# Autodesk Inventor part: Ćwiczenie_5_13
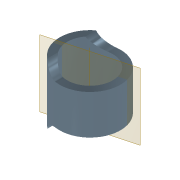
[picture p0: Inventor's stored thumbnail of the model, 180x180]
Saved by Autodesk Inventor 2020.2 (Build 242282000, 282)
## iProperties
Created: 2005-02
Part Number: Ćwiczenie_5_13
Document SubType Name: Modeling
Designer: F.Stasiak
Manufacturer: Standard
Standards Organization: Custom
Density: 1 g/cm^3
Material: Ogólny
Appearance: Nikiel (jasny)
Manager: www.cadconsulting.pl
Company: Fabian Stasiak CAD Consulting
Author: F.Stasiak
Subject: Zbiór ćwiczeń. Autodesk Inventor 2020. Kurs podstawowy
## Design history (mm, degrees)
sketch "Szkic1"
  geometry: C1 r 20 at (0, 0); 1 further point
  constraints: 1 centre point, 1 coincident
  dimensions: "d0" = 40 diameter of C1
extrude "Wyciągnięcie proste1" new body sketch "Szkic1" stored distance "d1" = 40; taper "d2" = 0 deg
sketch "Szkic2"
  geometry: L1 (20, -20)-(-20, -20) reference; L2 (-20, -20)-(-20, 20) reference; L3 (-20, 20)-(20, 20) reference; L4 (20, 20)-(20, -20) reference; L5 (20, 13)-(-2.461, 13); A1 r 10 centre (-2.461, 23) between (-12, 20) and (-2.461, 13)
  constraints: 10 end point, 2 horizontal, 2 point on circle, 2 point on line, 2 vertical, 1 centre point, 1 perpendicular, 1 tangent, 4 other
  dimensions: "d3" = 7 distance between parallel lines of L3 L5; "d4" = 10 radius of A1; "d5" = 8 distance from line of L2 A1.start
extrude "Wyciągnięcie proste2" cut sketch "Szkic2" extent not by distance; stored distance "d6" = 40; taper "d7" = 0 deg
mirror "Lustro1"
feature "Skorupa1" dims "d8" = 5
node "Oś konstrukcyjna1"
node "Płaszczyzna konstrukcyjna2"
node "Bryła1"
node "Korpusy bryłowe"
node "Korpusy powierzchniowe"
other parameters: "d16" = 15 deg
